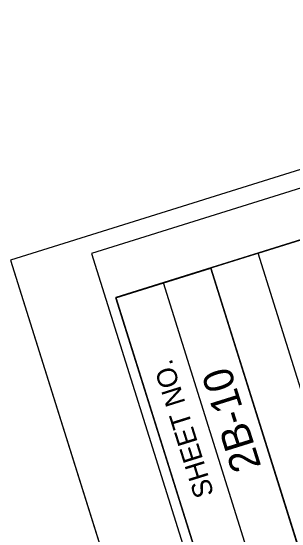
# Model space of a CAD drawing. Extents: x 473667 to 478950, y 494687 to 505998.
# Drawn here: x 473667.2 to 473738.2, y 505601.2 to 505733.3 of the extents above; entities that cross this region are included whole.
import ezdxf

# ---------------------------------------------------------------- set-up
doc = ezdxf.new("R2010")
doc.units = 0
for name, color, linetype in [('Sheet Cutting Line CELL', 7, 'Continuous'), ('Sheet Data Field CELL', 7, 'Continuous'), ('Sheet Plan CELL', 7, 'Continuous'), ('Sheet Plan Layout CELL', 7, 'Continuous'), ('Sheet Plot Border Inside CELL', 7, 'Continuous'), ('Sheet Plot Border Outside CELL', 7, 'Continuous')]:
    doc.layers.add(name, color=color, linetype=linetype)

msp = doc.modelspace()

# ---------------------------------------------------------------- linework, layer by layer
at = {"layer": 'Sheet Cutting Line CELL'}
msp.add_line((473667.17, 505670.37), (474170.46, 504063.86), dxfattribs=at)
at = {"layer": 'Sheet Plan CELL'}
for p, q in [((473777.45, 505477.47), (473717.62, 505668.35)), ((473777.45, 505477.47), (473717.62, 505668.35)), ((473765.49, 505473.71), (473705.69, 505664.61))]:
    msp.add_line(p, q, dxfattribs=at)
for points in [[(473693.71, 505660.9), (474142.15, 504229.46), (475144.13, 504543.36), (474695.69, 505974.78)], [(473759.45, 505576.68), (473729.55, 505672.09), (473836.91, 505705.74), (473866.82, 505610.31)], [(473753.51, 505469.97), (473693.71, 505660.9), (473717.62, 505668.35), (473777.45, 505477.47)]]:
    msp.add_lwpolyline(points, close=True, dxfattribs=at)
at = {"layer": 'Sheet Plan Layout CELL'}
msp.add_lwpolyline([(473967.06, 505495.78), (473895.53, 505724.11), (473693.7, 505660.91), (473765.24, 505432.55)], close=True, dxfattribs=at)
at = {"layer": 'Sheet Plot Border Inside CELL'}
msp.add_lwpolyline([(475192.41, 504397.64), (474694.35, 505987.44), (473687.6, 505672.06), (474185.66, 504082.25)], close=True, dxfattribs=at)
at = {"layer": 'Sheet Plot Border Outside CELL'}
msp.add_lwpolyline([(475215.38, 504391.22), (474712.1, 505997.73), (473667.17, 505670.37), (474170.46, 504063.86)], close=True, dxfattribs=at)

# ---------------------------------------------------------------- texts
at = {"layer": 'Sheet Data Field CELL'}
msp.add_text('2B-10', height=7.5, rotation=107.3948, dxfattribs=at).set_placement((473730.36, 505618.33))
at = {"layer": 'Sheet Plan CELL'}
msp.add_text('SHEET NO.', height=5, rotation=107.3948, dxfattribs=at).set_placement((473718.48, 505611.33))

doc.saveas('drawing.dxf')
